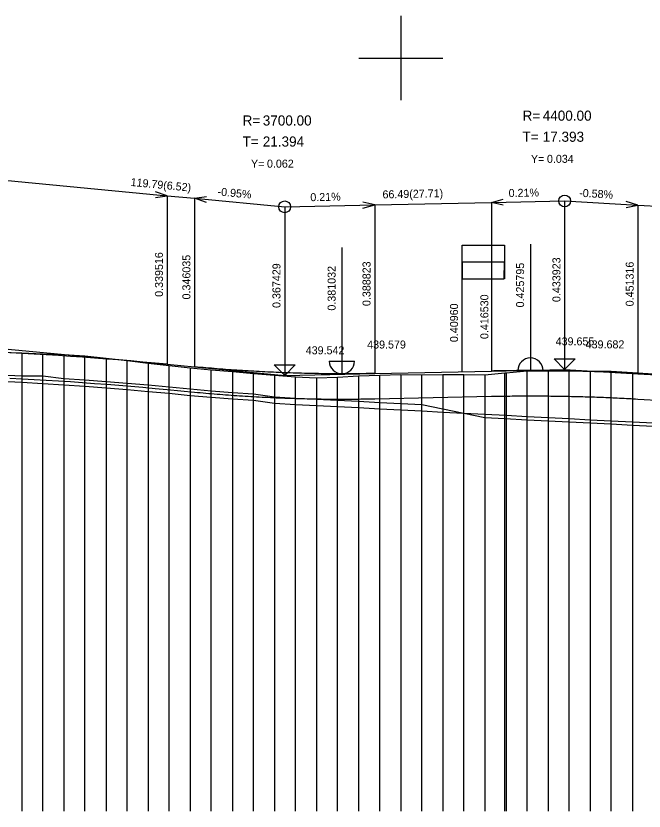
# Model space of a CAD drawing. Extents: x -240 to 1040, y 276 to 593.
# Drawn here: x 308.6 to 457.8, y 404 to 592.7 of the extents above; entities that cross this region are included whole.
import ezdxf

# ---------------------------------------------------------------- set-up
doc = ezdxf.new("R2010")
doc.units = 0
for name, color, linetype in [('1', 7, 'Continuous'), ('2', 7, 'Continuous'), ('FORMATY', 7, 'Continuous')]:
    doc.layers.add(name, color=color, linetype=linetype)

# ---------------------------------------------------------------- blocks, each defined once
blk = doc.blocks.new('INTRS')
for p, q in [((0, 29.99), (10, 30.04)), ((0, 26), (10, 26.02)), ((0, 22.01), (9.97, 22))]:
    blk.add_line(p, q)
blk.add_lwpolyline([(0, 22.01), (9.97, 22), (10, 26.02), (0, 26)], close=True)
at = {"layer": '2'}
for p, q in [((0, 0), (0, 30)), ((10, 30.04), (10, 22))]:
    blk.add_line(p, q, dxfattribs=at)

msp = doc.modelspace()

# ---------------------------------------------------------------- linework, layer by layer
at = {"layer": '1'}
for p, q in [((310, 512.67), (305, 512.87)), ((310, 512.67), (310, 404)), ((315, 512.47), (310, 512.67)), ((315, 404), (315, 512.47)), ((320, 512.26), (315, 512.47)), ((320, 512.26), (320, 404)), ((325, 511.96), (320, 512.26)), ((325, 404), (325, 511.96)), ((330, 511.4), (325, 511.96)), ((330, 511.4), (330, 404)), ((335, 510.83), (330, 511.4)), ((335, 404), (335, 510.83)), ((340, 510.27), (335, 510.83)), ((340, 510.27), (340, 404)), ((345, 509.71), (340, 510.27)), ((345, 404), (345, 509.71)), ((350, 509.15), (345, 509.71)), ((350, 509.15), (350, 404)), ((355, 508.67), (350, 509.15)), ((355, 404), (355, 508.67)), ((360, 508.25), (355, 508.67)), ((360, 508.25), (360, 404)), ((365, 507.82), (360, 508.25)), ((365, 404), (365, 507.82)), ((370, 507.4), (365, 507.82)), ((424.7, 507.95), (420, 507.5)), ((425, 507.98), (424.7, 507.95)), ((424.7, 404), (424.7, 507.95)), ((430, 508.38), (425, 507.98)), ((425, 507.98), (425, 404)), ((435, 508.43), (430, 508.38)), ((430, 404), (430, 508.38)), ((435, 508.43), (435, 404)), ((440, 508.38), (435, 508.43)), ((440, 404), (440, 508.38)), ((445, 508.35), (440, 508.38)), ((445, 508.35), (445, 404)), ((450, 508.31), (445, 508.35)), ((450, 404), (450, 508.31)), ((455, 508.06), (450, 508.31)), ((455, 508.06), (455, 404)), ((460, 507.74), (455, 508.06)), ((370, 507.4), (370, 404)), ((375, 506.98), (370, 507.4)), ((375, 404), (375, 506.98)), ((380, 506.72), (375, 506.98)), ((385, 506.95), (380, 506.72)), ((380, 506.72), (380, 404)), ((390, 507.21), (385, 506.95)), ((385, 404), (385, 506.95)), ((395, 507.41), (390, 507.21)), ((390, 507.21), (390, 404)), ((400, 507.57), (395, 507.41)), ((395, 404), (395, 507.41)), ((400, 507.57), (400, 404)), ((405, 507.44), (400, 507.57)), ((410, 507.53), (405, 507.44)), ((405, 404), (405, 507.44)), ((415, 507.57), (410, 507.53)), ((410, 507.53), (410, 404)), ((415, 404), (415, 507.57)), ((420, 507.5), (415, 507.57)), ((420, 507.5), (420, 404))]:
    msp.add_line(p, q, dxfattribs=at)
at = {"layer": '2'}
for p, q in [((252.64, 558.75), (344.52, 550.06)), ((344.52, 550.06), (341.72, 551.02)), ((341.72, 549.62), (344.52, 550.06)), ((344.52, 550.06), (344.52, 510.06)), ((344.52, 550.06), (351.04, 549.44)), ((351.04, 549.44), (353.84, 549.88)), ((351.04, 549.44), (351.04, 509.44)), ((353.84, 548.48), (351.04, 549.44)), ((351.04, 549.44), (372.43, 547.42)), ((372.43, 547.42), (393.82, 547.87)), ((372.43, 547.42), (372.43, 507.42)), ((393.82, 547.87), (391.02, 548.51)), ((391.02, 547.11), (393.82, 547.87)), ((393.82, 547.87), (421.53, 548.45)), ((393.82, 547.87), (393.82, 507.87)), ((421.53, 548.45), (424.33, 549.21)), ((421.53, 548.45), (438.92, 548.82)), ((421.53, 548.45), (421.53, 508.45)), ((424.33, 547.81), (421.53, 548.45)), ((438.92, 548.82), (438.92, 508.48)), ((438.92, 548.82), (456.32, 547.81)), ((456.32, 547.81), (453.52, 548.67)), ((453.52, 547.27), (456.32, 547.81)), ((456.32, 547.81), (456.32, 507.81)), ((456.32, 547.81), (489.93, 545.86)), ((430.79, 538.55), (430.79, 508.55)), ((386.03, 537.79), (386.03, 507.79)), ((252.64, 518.75), (344.52, 510.06)), ((310.06, 512.63), (307.19, 512.78)), ((312.93, 512.47), (310.06, 512.63)), ((315.81, 512.3), (312.93, 512.47)), ((318.68, 512.12), (315.81, 512.3)), ((321.55, 511.93), (318.68, 512.12)), ((324.42, 511.73), (321.55, 511.93)), ((327.29, 511.52), (324.42, 511.73)), ((330.16, 511.3), (327.29, 511.52)), ((333.03, 511.07), (330.16, 511.3)), ((335.9, 510.83), (333.03, 511.07)), ((338.77, 510.58), (335.9, 510.83)), ((341.65, 510.33), (338.77, 510.58)), ((344.52, 510.06), (341.65, 510.33)), ((344.52, 510.06), (351.04, 509.44)), ((372.43, 507.42), (369.93, 509.92)), ((369.93, 509.92), (374.93, 509.92)), ((374.93, 509.92), (372.43, 507.42)), ((383.03, 510.79), (389.03, 510.79)), ((438.92, 508.82), (436.42, 511.32)), ((436.42, 511.32), (441.42, 511.32)), ((441.42, 511.32), (438.92, 508.82)), ((351.7, 509.38), (351.04, 509.44)), ((351.04, 509.44), (372.43, 507.42)), ((352.37, 509.32), (351.7, 509.38)), ((353.04, 509.26), (352.37, 509.32)), ((353.71, 509.2), (353.04, 509.26)), ((354.38, 509.14), (353.71, 509.2)), ((355.05, 509.09), (354.38, 509.14)), ((355.72, 509.03), (355.05, 509.09)), ((356.38, 508.98), (355.72, 509.03)), ((357.05, 508.92), (356.38, 508.98)), ((357.72, 508.87), (357.05, 508.92)), ((358.39, 508.82), (357.72, 508.87)), ((359.06, 508.77), (358.39, 508.82)), ((359.73, 508.72), (359.06, 508.77)), ((360.4, 508.68), (359.73, 508.72)), ((361.06, 508.63), (360.4, 508.68)), ((361.73, 508.59), (361.06, 508.63)), ((362.4, 508.54), (361.73, 508.59)), ((363.07, 508.5), (362.4, 508.54)), ((363.74, 508.46), (363.07, 508.5)), ((364.41, 508.42), (363.74, 508.46)), ((365.07, 508.38), (364.41, 508.42)), ((365.74, 508.34), (365.07, 508.38)), ((366.41, 508.31), (365.74, 508.34)), ((367.08, 508.27), (366.41, 508.31)), ((367.75, 508.24), (367.08, 508.27)), ((368.42, 508.21), (367.75, 508.24)), ((369.09, 508.18), (368.42, 508.21)), ((369.75, 508.15), (369.09, 508.18)), ((370.42, 508.12), (369.75, 508.15)), ((371.09, 508.09), (370.42, 508.12)), ((371.76, 508.06), (371.09, 508.09)), ((372.43, 508.04), (371.76, 508.06)), ((373.1, 508.01), (372.43, 508.04)), ((372.43, 507.42), (393.82, 507.87)), ((373.77, 507.99), (373.1, 508.01)), ((374.43, 507.97), (373.77, 507.99)), ((375.1, 507.95), (374.43, 507.97)), ((375.77, 507.93), (375.1, 507.95)), ((376.44, 507.91), (375.77, 507.93)), ((377.11, 507.9), (376.44, 507.91)), ((377.78, 507.88), (377.11, 507.9)), ((378.45, 507.87), (377.78, 507.88)), ((379.11, 507.85), (378.45, 507.87)), ((379.78, 507.84), (379.11, 507.85)), ((380.45, 507.83), (379.78, 507.84)), ((381.12, 507.82), (380.45, 507.83)), ((381.79, 507.81), (381.12, 507.82)), ((382.46, 507.81), (381.79, 507.81)), ((383.13, 507.8), (382.46, 507.81)), ((383.79, 507.8), (383.13, 507.8)), ((384.46, 507.79), (383.79, 507.8)), ((385.13, 507.79), (384.46, 507.79)), ((385.8, 507.79), (385.13, 507.79)), ((386.47, 507.79), (385.8, 507.79)), ((387.14, 507.79), (386.47, 507.79)), ((387.81, 507.79), (387.14, 507.79)), ((388.47, 507.8), (387.81, 507.79)), ((389.14, 507.8), (388.47, 507.8)), ((389.81, 507.81), (389.14, 507.8)), ((390.48, 507.82), (389.81, 507.81)), ((391.15, 507.82), (390.48, 507.82)), ((391.82, 507.83), (391.15, 507.82)), ((392.49, 507.84), (391.82, 507.83)), ((393.15, 507.86), (392.49, 507.84)), ((393.82, 507.87), (393.15, 507.86)), ((393.82, 507.87), (421.53, 508.45)), ((421.53, 508.45), (438.92, 508.82)), ((422.07, 508.47), (421.53, 508.45)), ((422.62, 508.48), (422.07, 508.47)), ((423.16, 508.49), (422.62, 508.48)), ((423.7, 508.49), (423.16, 508.49)), ((424.25, 508.5), (423.7, 508.49)), ((424.79, 508.51), (424.25, 508.5)), ((425.33, 508.52), (424.79, 508.51)), ((425.88, 508.52), (425.33, 508.52)), ((426.42, 508.53), (425.88, 508.52)), ((426.97, 508.53), (426.42, 508.53)), ((427.51, 508.54), (426.97, 508.53)), ((428.05, 508.54), (427.51, 508.54)), ((433.79, 508.55), (427.79, 508.55)), ((428.6, 508.55), (428.05, 508.54)), ((429.14, 508.55), (428.6, 508.55)), ((429.68, 508.55), (429.14, 508.55)), ((430.23, 508.55), (429.68, 508.55)), ((430.77, 508.55), (430.23, 508.55)), ((431.31, 508.55), (430.77, 508.55)), ((431.86, 508.55), (431.31, 508.55)), ((432.4, 508.55), (431.86, 508.55)), ((432.94, 508.55), (432.4, 508.55)), ((433.49, 508.54), (432.94, 508.55)), ((434.03, 508.54), (433.49, 508.54)), ((434.57, 508.54), (434.03, 508.54)), ((435.12, 508.53), (434.57, 508.54)), ((435.66, 508.52), (435.12, 508.53)), ((436.21, 508.52), (435.66, 508.52)), ((436.75, 508.51), (436.21, 508.52)), ((437.29, 508.5), (436.75, 508.51)), ((437.84, 508.5), (437.29, 508.5)), ((438.38, 508.49), (437.84, 508.5)), ((438.92, 508.48), (438.38, 508.49)), ((438.92, 508.82), (456.32, 507.81)), ((439.47, 508.47), (438.92, 508.48)), ((440.01, 508.45), (439.47, 508.47)), ((440.55, 508.44), (440.01, 508.45)), ((441.1, 508.43), (440.55, 508.44)), ((441.64, 508.42), (441.1, 508.43)), ((442.18, 508.4), (441.64, 508.42)), ((442.73, 508.39), (442.18, 508.4)), ((443.27, 508.37), (442.73, 508.39)), ((443.81, 508.36), (443.27, 508.37)), ((444.36, 508.34), (443.81, 508.36)), ((444.9, 508.33), (444.36, 508.34)), ((445.45, 508.31), (444.9, 508.33)), ((445.99, 508.29), (445.45, 508.31)), ((446.53, 508.27), (445.99, 508.29)), ((447.08, 508.25), (446.53, 508.27)), ((447.62, 508.23), (447.08, 508.25)), ((448.16, 508.21), (447.62, 508.23)), ((448.71, 508.19), (448.16, 508.21)), ((449.25, 508.16), (448.71, 508.19)), ((449.79, 508.14), (449.25, 508.16)), ((450.34, 508.12), (449.79, 508.14)), ((450.88, 508.09), (450.34, 508.12)), ((451.42, 508.07), (450.88, 508.09)), ((451.97, 508.04), (451.42, 508.07)), ((452.51, 508.02), (451.97, 508.04)), ((453.06, 507.99), (452.51, 508.02)), ((453.6, 507.96), (453.06, 507.99)), ((454.14, 507.93), (453.6, 507.96)), ((454.69, 507.9), (454.14, 507.93)), ((455.23, 507.87), (454.69, 507.9)), ((455.77, 507.84), (455.23, 507.87)), ((456.32, 507.81), (455.77, 507.84)), ((456.32, 507.81), (489.93, 505.86)), ((307.19, 506.78), (310.06, 506.63)), ((310.06, 506.63), (312.93, 506.47)), ((312.93, 506.47), (315.81, 506.3)), ((315.81, 506.3), (318.68, 506.12)), ((318.68, 506.12), (321.55, 505.93)), ((321.55, 505.93), (324.42, 505.73)), ((324.42, 505.73), (327.29, 505.52)), ((327.29, 505.52), (330.16, 505.3)), ((330.16, 505.3), (333.03, 505.07)), ((333.03, 505.07), (335.9, 504.83)), ((335.9, 504.83), (338.77, 504.58)), ((338.77, 504.58), (341.65, 504.33)), ((340, 505.15), (345, 504.69)), ((341.65, 504.33), (344.52, 504.06)), ((344.52, 504.06), (351.04, 503.44)), ((345, 504.69), (350, 504.22)), ((350, 504.22), (355, 503.76)), ((340, 503.62), (345, 503.16)), ((345, 503.16), (350, 502.68)), ((350, 502.68), (355, 502.23)), ((351.04, 503.44), (351.7, 503.38)), ((351.7, 503.38), (352.37, 503.32)), ((352.37, 503.32), (353.04, 503.26)), ((353.04, 503.26), (353.71, 503.2)), ((353.71, 503.2), (354.38, 503.14)), ((354.38, 503.14), (355.05, 503.09)), ((355, 503.76), (360, 503.38)), ((355, 502.23), (360, 501.85)), ((355.05, 503.09), (355.72, 503.03)), ((355.72, 503.03), (356.38, 502.98)), ((356.38, 502.98), (357.05, 502.92)), ((357.05, 502.92), (357.72, 502.87)), ((357.72, 502.87), (358.39, 502.82)), ((358.39, 502.82), (359.06, 502.77)), ((359.06, 502.77), (359.73, 502.72)), ((359.73, 502.72), (360.4, 502.68)), ((360, 503.38), (365, 503.06)), ((360.4, 502.68), (361.06, 502.63)), ((361.06, 502.63), (361.73, 502.59)), ((361.73, 502.59), (362.4, 502.54)), ((362.4, 502.54), (363.07, 502.5)), ((363.07, 502.5), (363.74, 502.46)), ((363.74, 502.46), (364.41, 502.42)), ((364.41, 502.42), (365.07, 502.38)), ((365, 503.06), (370, 502.3)), ((365.07, 502.38), (365.74, 502.34)), ((365.74, 502.34), (366.41, 502.31)), ((366.41, 502.31), (367.08, 502.27)), ((367.08, 502.27), (367.75, 502.24)), ((367.75, 502.24), (368.42, 502.21)), ((368.42, 502.21), (369.09, 502.18)), ((369.09, 502.18), (369.75, 502.15)), ((369.75, 502.15), (370.42, 502.12)), ((370, 502.3), (375, 502.04)), ((370.42, 502.12), (371.09, 502.09)), ((371.09, 502.09), (371.76, 502.06)), ((371.76, 502.06), (372.43, 502.04)), ((375, 502.04), (380, 501.79)), ((393.82, 501.87), (421.53, 502.45)), ((421.53, 502.45), (422.07, 502.47)), ((422.07, 502.47), (422.62, 502.48)), ((422.62, 502.48), (423.16, 502.49)), ((423.16, 502.49), (423.7, 502.49)), ((423.7, 502.49), (424.25, 502.5)), ((424.25, 502.5), (424.79, 502.51)), ((424.79, 502.51), (425.33, 502.52)), ((425.33, 502.52), (425.88, 502.52)), ((425.88, 502.52), (426.42, 502.53)), ((426.42, 502.53), (426.97, 502.53)), ((426.97, 502.53), (427.51, 502.54)), ((427.51, 502.54), (428.05, 502.54)), ((428.05, 502.54), (428.6, 502.55)), ((428.6, 502.55), (429.14, 502.55)), ((429.14, 502.55), (429.68, 502.55)), ((429.68, 502.55), (430.23, 502.55)), ((430.23, 502.55), (430.77, 502.55)), ((430.77, 502.55), (431.31, 502.55)), ((431.31, 502.55), (431.86, 502.55)), ((431.86, 502.55), (432.4, 502.55)), ((432.4, 502.55), (432.94, 502.55)), ((432.94, 502.55), (433.49, 502.54)), ((433.49, 502.54), (434.03, 502.54)), ((434.03, 502.54), (434.57, 502.54)), ((434.57, 502.54), (435.12, 502.53)), ((435.12, 502.53), (435.66, 502.52)), ((435.66, 502.52), (436.21, 502.52)), ((436.21, 502.52), (436.75, 502.51)), ((436.75, 502.51), (437.29, 502.5)), ((437.29, 502.5), (437.84, 502.5)), ((437.84, 502.5), (438.38, 502.49)), ((438.38, 502.49), (438.92, 502.48)), ((438.92, 502.48), (439.47, 502.47)), ((439.47, 502.47), (440.01, 502.45)), ((440.01, 502.45), (440.55, 502.44)), ((440.55, 502.44), (441.1, 502.43)), ((441.1, 502.43), (441.64, 502.42)), ((441.64, 502.42), (442.18, 502.4)), ((442.18, 502.4), (442.73, 502.39)), ((442.73, 502.39), (443.27, 502.37)), ((443.27, 502.37), (443.81, 502.36)), ((443.81, 502.36), (444.36, 502.34)), ((444.36, 502.34), (444.9, 502.33)), ((444.9, 502.33), (445.45, 502.31)), ((445.45, 502.31), (445.99, 502.29)), ((445.99, 502.29), (446.53, 502.27)), ((446.53, 502.27), (447.08, 502.25)), ((447.08, 502.25), (447.62, 502.23)), ((447.62, 502.23), (448.16, 502.21)), ((448.16, 502.21), (448.71, 502.19)), ((448.71, 502.19), (449.25, 502.16)), ((449.25, 502.16), (449.79, 502.14)), ((449.79, 502.14), (450.34, 502.12)), ((450.34, 502.12), (450.88, 502.09)), ((450.88, 502.09), (451.42, 502.07)), ((451.42, 502.07), (451.97, 502.04)), ((360, 501.85), (365, 501.53)), ((365, 501.53), (370, 500.8)), ((370, 500.8), (375, 500.54)), ((372.43, 502.04), (373.1, 502.01)), ((373.1, 502.01), (373.77, 501.99)), ((373.77, 501.99), (374.43, 501.97)), ((374.43, 501.97), (375.1, 501.95)), ((375, 500.54), (380, 500.28)), ((375.1, 501.95), (375.77, 501.93)), ((375.77, 501.93), (376.44, 501.91)), ((376.44, 501.91), (377.11, 501.9)), ((377.11, 501.9), (377.78, 501.88)), ((377.78, 501.88), (378.45, 501.87)), ((378.45, 501.87), (379.11, 501.85)), ((379.11, 501.85), (379.78, 501.84)), ((379.78, 501.84), (380.45, 501.83)), ((380, 501.79), (385, 501.53)), ((380, 500.28), (385, 500.02)), ((380.45, 501.83), (381.12, 501.82)), ((381.12, 501.82), (381.79, 501.81)), ((381.79, 501.81), (382.46, 501.81)), ((382.46, 501.81), (383.13, 501.8)), ((383.13, 501.8), (383.79, 501.8)), ((383.79, 501.8), (384.46, 501.79)), ((384.46, 501.79), (385.13, 501.79)), ((385, 501.53), (390, 501.27)), ((385.13, 501.79), (385.8, 501.79)), ((385.8, 501.79), (386.47, 501.79)), ((386.47, 501.79), (387.14, 501.79)), ((387.14, 501.79), (387.81, 501.79)), ((387.81, 501.79), (388.47, 501.8)), ((388.47, 501.8), (389.14, 501.8)), ((389.14, 501.8), (389.81, 501.81)), ((389.81, 501.81), (390.48, 501.82)), ((390, 501.27), (395, 501.01)), ((390.48, 501.82), (391.15, 501.82)), ((391.15, 501.82), (391.82, 501.83)), ((391.82, 501.83), (392.49, 501.84)), ((392.49, 501.84), (393.15, 501.86)), ((393.15, 501.86), (393.82, 501.87)), ((395, 501.01), (400, 500.76)), ((400, 500.76), (405, 500.5)), ((405, 500.5), (410, 499.47)), ((451.97, 502.04), (452.51, 502.02)), ((452.51, 502.02), (453.06, 501.99)), ((453.06, 501.99), (453.6, 501.96)), ((453.6, 501.96), (454.14, 501.93)), ((454.14, 501.93), (454.69, 501.9)), ((454.69, 501.9), (455.23, 501.87)), ((455.23, 501.87), (455.77, 501.84)), ((455.77, 501.84), (456.32, 501.81)), ((456.32, 501.81), (489.93, 499.86)), ((385, 500.02), (390, 499.76)), ((390, 499.76), (395, 499.5)), ((395, 499.5), (400, 499.24)), ((400, 499.24), (405, 498.98)), ((405, 498.98), (410, 498.72))]:
    msp.add_line(p, q, dxfattribs=at)
for points in [[(305, 507.56), (310, 507.31), (315, 507.31), (320, 506.7), (325, 506.36), (330, 505.98), (335, 505.58), (340, 505.15), (345, 504.69), (350, 504.22), (355, 503.76), (360, 503.38), (365, 503.06), (370, 502.3), (375, 502.04), (380, 501.79), (385, 501.53), (390, 501.27), (395, 501.01), (400, 500.76), (405, 500.5), (410, 499.47), (415, 498.43), (420, 497.4), (424.7, 497.16), (430, 496.9), (435, 496.64), (440, 496.39), (445, 496.14), (450, 495.89), (455, 495.63), (460, 495.38)], [(305, 506.03), (310, 505.77), (315, 505.49), (320, 505.17), (325, 504.83), (330, 504.45), (335, 504.05), (340, 503.62), (345, 503.16), (350, 502.68), (355, 502.23), (360, 501.85), (365, 501.53), (370, 500.8), (375, 500.54), (380, 500.28), (385, 500.02), (390, 499.76), (395, 499.5), (400, 499.24), (405, 498.98), (410, 498.72), (415, 498.46), (420, 498.2), (425, 497.94), (430, 497.68), (435, 497.42), (440, 497.16), (445, 496.9), (450, 496.64), (455, 496.38), (460, 496.12)]]:
    msp.add_lwpolyline(points, dxfattribs=at)
for centre in [(438.92, 548.82), (372.43, 547.42)]:
    msp.add_circle(centre, 1.4, dxfattribs=at)
for centre, start, end in [((430.79, 508.55), 0, 180), ((386.03, 510.79), 180, 0)]:
    msp.add_arc(centre, 3, start, end, dxfattribs=at)
at = {"layer": 'FORMATY'}
for p, q in [((400.02, 592.74), (400.02, 572.74)), ((400.02, 592.74), (400.02, 572.74)), ((400.02, 592.74), (400.02, 572.74)), ((400.02, 592.74), (400.02, 572.74)), ((400.02, 592.74), (400.02, 572.74)), ((400.02, 592.74), (400.02, 572.74)), ((390.02, 582.74), (410.02, 582.74)), ((390.02, 582.74), (410.02, 582.74)), ((390.02, 582.74), (410.02, 582.74)), ((390.02, 582.74), (410.02, 582.74)), ((390.02, 582.74), (410.02, 582.74)), ((390.02, 582.74), (410.02, 582.74))]:
    msp.add_line(p, q, dxfattribs=at)

# ---------------------------------------------------------------- block references
msp.add_blockref('INTRS', (414.6, 508.31))

# ---------------------------------------------------------------- texts
msp.add_text('0.40960', height=1.9, rotation=90).set_placement((413.6, 515.31))
at = {"layer": '2'}
for s, height, p in [('R=', 2.4, (428.92, 567.86)), ('4400.00', 2.4, (433.72, 567.86)), ('R=', 2.4, (362.43, 566.72)), ('3700.00', 2.4, (367.23, 566.72)), ('T=', 2.4, (428.92, 562.86)), ('17.393', 2.4, (433.72, 562.86)), ('T=', 2.4, (362.43, 561.72)), ('21.394', 2.4, (367.23, 561.72)), ('Y=', 1.9, (430.92, 557.86)), ('0.034', 1.9, (434.72, 557.86)), ('Y=', 1.9, (364.43, 556.72)), ('0.062', 1.9, (368.23, 556.72)), ('439.579', 1.9, (392.03, 513.79)), ('439.655', 1.9, (436.79, 514.55)), ('439.682', 1.9, (443.92, 513.82)), ('439.542', 1.9, (377.43, 512.42))]:
    msp.add_text(s, height=height, dxfattribs=at).set_placement(p)
for s, rotation, p in [('119.79(6.52)', 354.5967, (335.78, 552.39)), (' -0.95%', 354.5967, (355.73, 550.2)), ('66.49(27.71)', 1.2063, (395.68, 549.41)), ('  0.21%', 1.2063, (424.23, 549.71)), (' -0.58%', 356.6804, (441.62, 549.86)), ('  0.21%', 1.2063, (377.13, 548.72)), ('0.339516', 90, (343.52, 526.06)), ('0.346035', 90, (350.04, 525.44)), ('0.388823', 90, (392.82, 523.87)), ('0.433923', 90, (437.92, 524.82)), ('0.451316', 90, (455.32, 523.81)), ('0.367429', 90, (371.43, 523.42)), ('0.381032', 90, (384.53, 522.79)), ('0.425795', 90, (429.29, 523.55)), ('0.416530', 90, (420.81, 516.04))]:
    msp.add_text(s, height=1.9, rotation=rotation, dxfattribs=at).set_placement(p)

doc.saveas('drawing.dxf')
